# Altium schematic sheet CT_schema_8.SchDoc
size 287 x 160 mm
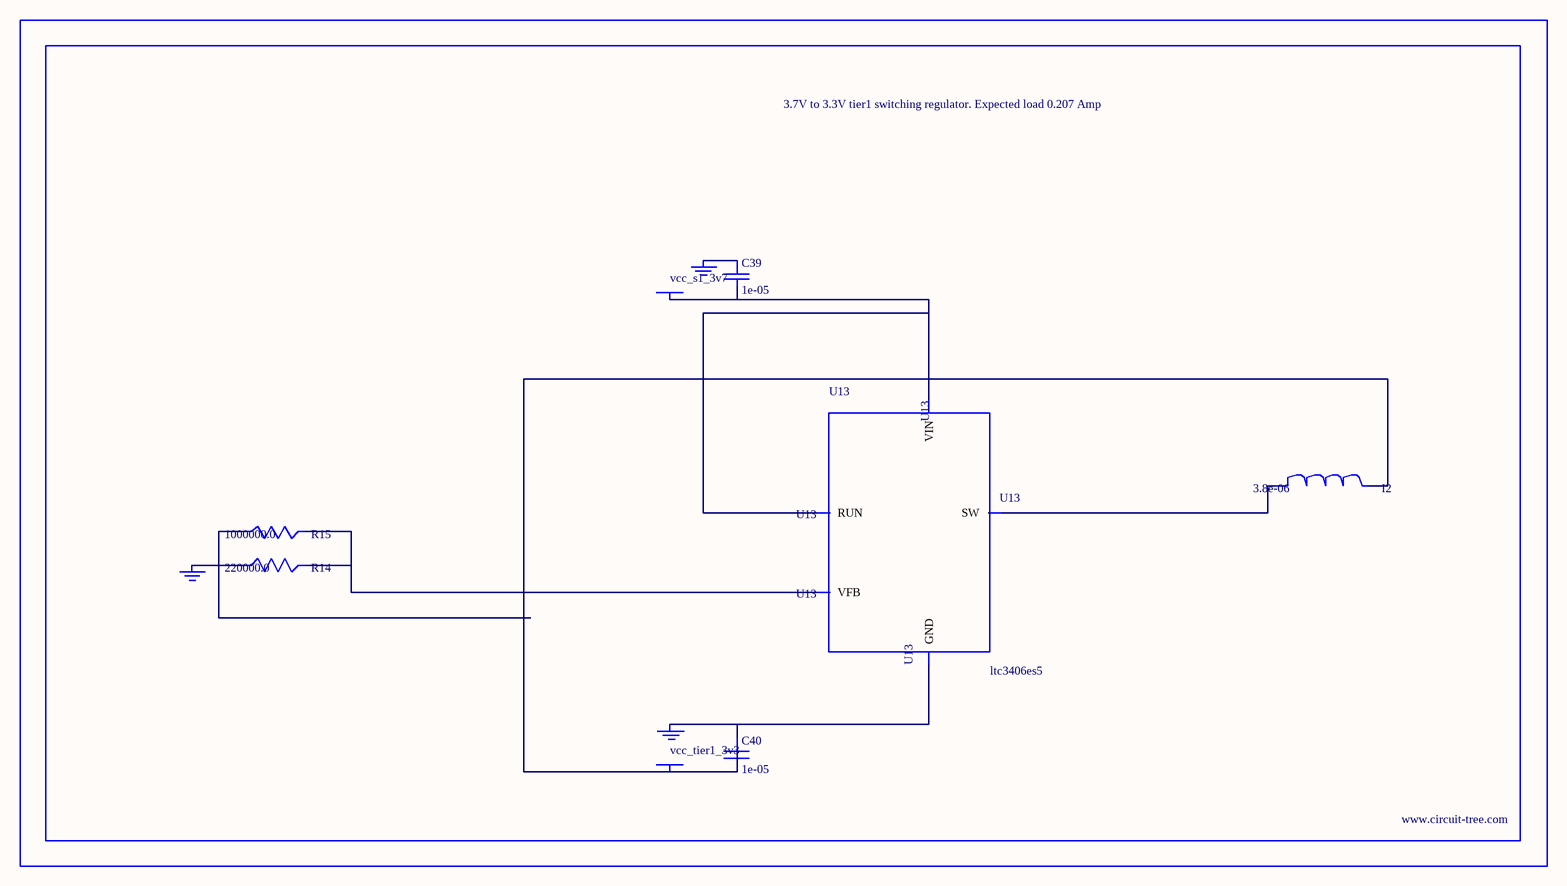
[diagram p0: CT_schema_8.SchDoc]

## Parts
BORDER7  (no value)
C39  1e-05  [C0805]
C40  1e-05  [C0805]
GND_INSTANCE_7_0  (no value)
GND_INSTANCE_7_1  (no value)
GND_INSTANCE_7_2  (no value)
I2  3.8e-06  [DR1040]
POWER_INSTANCE_7_0  vcc_tier1_3v3
POWER_INSTANCE_7_1  vcc_s1_3v7
R14  220000.0  [R0603]
R15  1000000.0  [R0603]
U13  ltc3406es5  [TSOT-23-5]

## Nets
NetC39_1: C39.1 GND_INSTANCE_7_1.0(GND)
NetC39_2: C39.2 POWER_INSTANCE_7_1.0(PWR) U13.1(RUN) U13.4(VIN)
NetC40_1: C40.1 GND_INSTANCE_7_0.0(GND) U13.2(GND)
NetC40_2: C40.2 I2.2 POWER_INSTANCE_7_0.0(PWR) R15.1
NetGND_INSTANCE_7_2_0: GND_INSTANCE_7_2.0(GND) R14.1
NetI2_1: I2.1 U13.3(SW)
NetR14_2: R14.2 R15.2 U13.5(VFB)

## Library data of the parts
BORDER7 = BORDER_PAGE7
C39 C40 = C0805C106K8RACTU
GND_INSTANCE_7_0-GND_INSTANCE_7_2 = GND
I2 = DR1040-3R8-R
POWER_INSTANCE_7_0 POWER_INSTANCE_7_1 = PWR
R14 = RC0603JR-07220KL
R15 = RC0603JR-071ML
